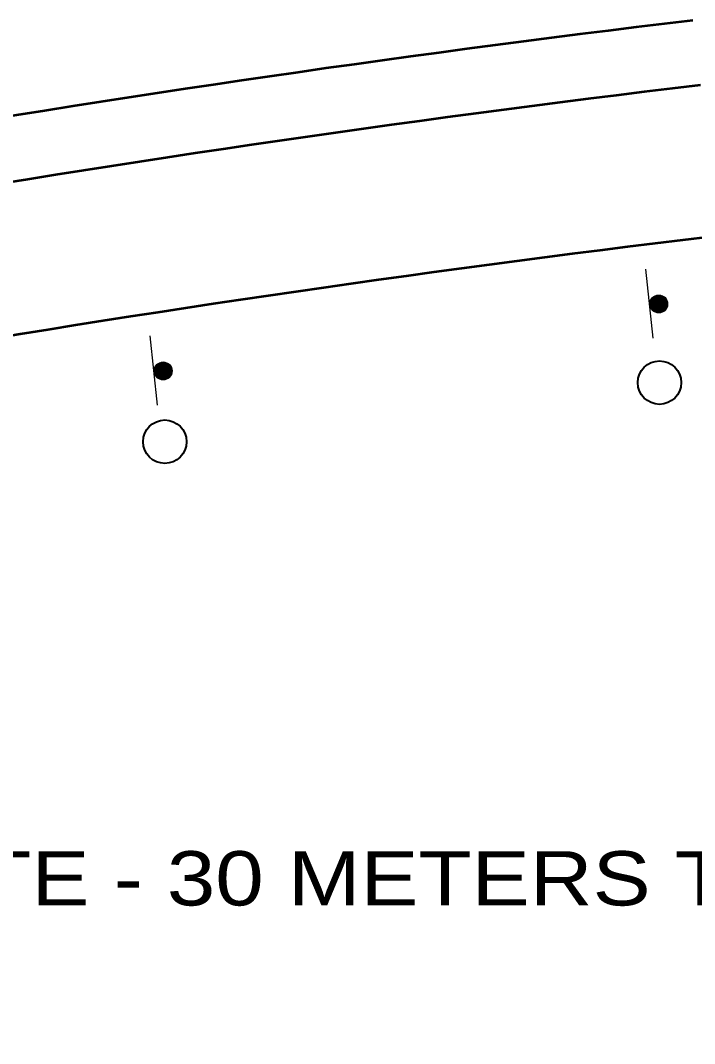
# Model space of a CAD drawing. Extents: x 393 to 1249, y -102 to 530.
# Drawn here: x 648.12 to 678.31, y 284.57 to 330.37 of the extents above; entities that cross this region are included whole.
import ezdxf
from ezdxf.enums import TextEntityAlignment as Align

# ---------------------------------------------------------------- set-up
doc = ezdxf.new("R2010")
doc.units = 0
doc.header["$LTSCALE"] = 0.97
doc.layers.add('1', color=7, linetype='Continuous', lineweight=40)
doc.layers.add('4', color=7, linetype='Continuous', lineweight=25)

msp = doc.modelspace()

# ---------------------------------------------------------------- linework, layer by layer
at = {"layer": '1'}
for centre, radius in [((676.7094, 317.6715), 0.3791), ((676.7008, 317.6608), 0.35), ((676.7105, 317.6618), 0.3305), ((676.7267, 317.6929), 0.3402), ((676.7094, 317.6715), 0.3013), ((676.7094, 317.6715), 0.2819), ((676.7105, 317.6618), 0.2722), ((676.7105, 317.6618), 0.2527), ((676.7201, 317.6629), 0.2335), ((676.7298, 317.6639), 0.2138), ((676.7298, 317.6639), 0.1944), ((676.7125, 317.6425), 0.1555), ((676.7491, 317.6659), 0.175), ((676.7115, 317.6522), 0.1069), ((676.7705, 317.6486), 0.1555), ((676.7791, 317.6593), 0.1461), ((676.7898, 317.6506), 0.1166), ((676.7995, 317.6516), 0.0977), ((676.7339, 317.8109), 0.00972), ((676.8092, 317.6527), 0.0778), ((676.8285, 317.6547), 0.0583), ((676.8478, 317.6567), 0.0389), ((676.8672, 317.6588), 0.0194), ((676.7442, 314.1564), 0.972), ((654.5111, 314.6735), 0.3791), ((654.5025, 314.6629), 0.35), ((654.5122, 314.6639), 0.3305), ((654.5284, 314.6949), 0.3402), ((654.5111, 314.6735), 0.3013), ((654.5111, 314.6735), 0.2819), ((654.5122, 314.6639), 0.2722), ((654.5122, 314.6639), 0.2527), ((654.5218, 314.6649), 0.2335), ((654.5315, 314.6659), 0.2138), ((654.5315, 314.6659), 0.1944), ((654.5142, 314.6445), 0.1555), ((654.5508, 314.6679), 0.175), ((654.5132, 314.6542), 0.1069), ((654.5722, 314.6506), 0.1555), ((654.5808, 314.6613), 0.1461), ((654.5915, 314.6527), 0.1166), ((654.6012, 314.6537), 0.0977), ((654.5356, 314.8129), 0.00972), ((654.6109, 314.6547), 0.0778), ((654.6302, 314.6567), 0.0583), ((654.6495, 314.6588), 0.0389), ((654.6689, 314.6608), 0.0194), ((654.5836, 311.5135), 0.972)]:
    msp.add_circle(centre, radius, dxfattribs=at)
at = {"layer": '1', "lineweight": 53}
msp.add_arc((765.1387, -401.6361), 727.4371, 96.79853, 109.38334, dxfattribs=at)
for major_axis, ratio, end_param in [((-249.7657, 693.037), 0.999341, 6.2772858), ((-248.777, 690.2937), 0.999339, 6.2770997)]:
    msp.add_ellipse((765.4392, -401.0949), major_axis=major_axis, ratio=ratio, start_param=6.0557933, end_param=end_param, dxfattribs=at)
at = {"layer": '4'}
for p, q in [((676.4589, 316.15), (676.1336, 319.2433)), ((654.2606, 313.152), (653.9353, 316.2453))]:
    msp.add_line(p, q, dxfattribs=at)
for centre in [(676.7084, 317.6812), (654.5101, 314.6832)]:
    msp.add_circle(centre, 0.3985, dxfattribs=at)

# ---------------------------------------------------------------- texts
at = {"layer": '1', "width": 1.2}
msp.add_text('WHITE - 30 METERS THRU INTERCHANGE', height=2.43, dxfattribs=at).set_placement((678.1883, 290.7508), align=Align.CENTER)

doc.saveas('drawing.dxf')
